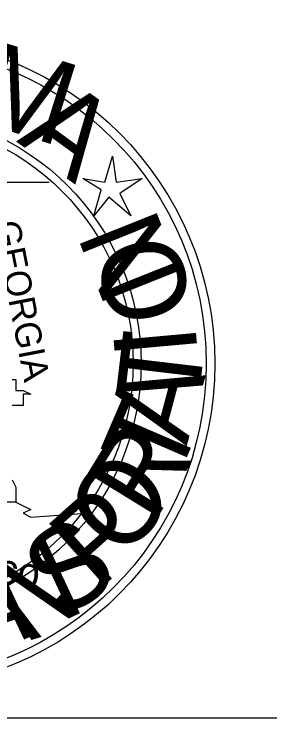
# Model space of a CAD drawing. Extents: x 1797478 to 1804836, y 246529 to 250952.
# Drawn here: x 1802983.3 to 1802986.92, y 250069.42 to 250079.37 of the extents above; entities that cross this region are included whole.
import ezdxf

# ---------------------------------------------------------------- set-up
doc = ezdxf.new("R2010")
doc.units = 0
doc.layers.add('great seal', color=7, linetype='Continuous')
doc.layers.add('SHT-BNDRY', color=7, linetype='Continuous')

msp = doc.modelspace()

# ---------------------------------------------------------------- linework, layer by layer
at = {"layer": 'great seal'}
msp.add_line((1802982.5334, 250076.9902), (1802983.7947, 250076.9902), dxfattribs=at)
msp.add_line((1802982.5334, 250076.9902), (1802983.7947, 250076.9902), dxfattribs=at)
msp.add_line((1802982.5334, 250076.9902), (1802983.7947, 250076.9902), dxfattribs=at)
msp.add_lwpolyline([(1802984.688, 250077.358), (1802984.7406, 250076.9902), (1802985.1085, 250077.0427), (1802984.7932, 250076.8325), (1802984.9508, 250076.5172), (1802984.6355, 250076.78), (1802984.4253, 250076.5172), (1802984.5304, 250076.8851), (1802984.2676, 250077.0427), (1802984.5829, 250076.9902)], close=True, dxfattribs=at)
msp.add_lwpolyline([(1802984.688, 250077.358), (1802984.7406, 250076.9902), (1802985.1085, 250077.0427), (1802984.7932, 250076.8325), (1802984.9508, 250076.5172), (1802984.6355, 250076.78), (1802984.4253, 250076.5172), (1802984.5304, 250076.8851), (1802984.2676, 250077.0427), (1802984.5829, 250076.9902)], close=True, dxfattribs=at)
msp.add_lwpolyline([(1802984.688, 250077.358), (1802984.7406, 250076.9902), (1802985.1085, 250077.0427), (1802984.7932, 250076.8325), (1802984.9508, 250076.5172), (1802984.6355, 250076.78), (1802984.4253, 250076.5172), (1802984.5304, 250076.8851), (1802984.2676, 250077.0427), (1802984.5829, 250076.9902)], close=True, dxfattribs=at)
for points in [[(1802983.2691, 250074.2049), (1802983.3217, 250074.2049), (1802983.3217, 250074.1523), (1802983.3217, 250074.1523), (1802983.3217, 250074.0998), (1802983.3217, 250074.0472), (1802983.4268, 250074.0472), (1802983.5319, 250073.9947), (1802983.4268, 250073.9947), (1802983.4268, 250073.837), (1802983.4268, 250073.837), (1802983.3217, 250073.837), (1802983.3217, 250073.837), (1802983.3217, 250073.837), (1802983.3217, 250073.837), (1802983.2691, 250073.837)], [(1802983.2691, 250074.2049), (1802983.3217, 250074.2049), (1802983.3217, 250074.1523), (1802983.3217, 250074.1523), (1802983.3217, 250074.0998), (1802983.3217, 250074.0472), (1802983.4268, 250074.0472), (1802983.5319, 250073.9947), (1802983.4268, 250073.9947), (1802983.4268, 250073.837), (1802983.4268, 250073.837), (1802983.3217, 250073.837), (1802983.3217, 250073.837), (1802983.3217, 250073.837), (1802983.3217, 250073.837), (1802983.2691, 250073.837)], [(1802983.2691, 250074.2049), (1802983.3217, 250074.2049), (1802983.3217, 250074.1523), (1802983.3217, 250074.1523), (1802983.3217, 250074.0998), (1802983.3217, 250074.0472), (1802983.4268, 250074.0472), (1802983.5319, 250073.9947), (1802983.4268, 250073.9947), (1802983.4268, 250073.837), (1802983.4268, 250073.837), (1802983.3217, 250073.837), (1802983.3217, 250073.837), (1802983.3217, 250073.837), (1802983.3217, 250073.837), (1802983.2691, 250073.837)], [(1802983.2691, 250072.786), (1802983.3217, 250072.6809), (1802983.3217, 250072.6809), (1802983.3217, 250072.6283), (1802983.3217, 250072.6283), (1802983.3217, 250072.4706), (1802980.6415, 250072.4706)], [(1802983.2691, 250072.786), (1802983.3217, 250072.6809), (1802983.3217, 250072.6809), (1802983.3217, 250072.6283), (1802983.3217, 250072.6283), (1802983.3217, 250072.4706), (1802980.6415, 250072.4706)], [(1802983.2691, 250072.786), (1802983.3217, 250072.6809), (1802983.3217, 250072.6809), (1802983.3217, 250072.6283), (1802983.3217, 250072.6283), (1802983.3217, 250072.4706), (1802980.6415, 250072.4706)], [(1802983.3217, 250072.4706), (1802983.4268, 250072.4181), (1802983.4268, 250072.4181), (1802983.5319, 250072.3655), (1802983.4268, 250072.313), (1802983.5319, 250072.2604), (1802984.3202, 250072.313)], [(1802983.3217, 250072.4706), (1802983.4268, 250072.4181), (1802983.4268, 250072.4181), (1802983.5319, 250072.3655), (1802983.4268, 250072.313), (1802983.5319, 250072.2604), (1802984.3202, 250072.313)], [(1802983.3217, 250072.4706), (1802983.4268, 250072.4181), (1802983.4268, 250072.4181), (1802983.5319, 250072.3655), (1802983.4268, 250072.313), (1802983.5319, 250072.2604), (1802984.3202, 250072.313)]]:
    msp.add_lwpolyline(points, dxfattribs=at)
for radius in [4.5988, 4.5988, 4.5988, 4.4778, 4.4778, 4.4778, 3.5557, 3.5557, 3.5557, 3.4444, 3.4444, 3.4444]:
    msp.add_circle((1802981.5384, 250074.4308), radius, dxfattribs=at)
at = {"layer": 'SHT-BNDRY'}
msp.add_lwpolyline([(1802808.5046, 250069.422), (1803131.0046, 250069.422), (1803131.0046, 250279.422), (1802808.5046, 250279.422)], close=True, dxfattribs=at)

# ---------------------------------------------------------------- texts
at = {"layer": 'great seal'}
for s, height, rotation, p in [('M', 1.1701, 342.59208, (1802982.691, 250077.8836)), ('A', 1.1695, 323.98869, (1802983.3217, 250077.5683)), ('A', 1.1695, 323.98869, (1802983.3217, 250077.5683)), ('A', 1.1695, 323.98869, (1802983.3217, 250077.5683)), ('N', 1.1701, 111.72097, (1802985.6866, 250075.6238)), ('N', 1.1701, 111.72097, (1802985.6866, 250075.6238)), ('N', 1.1701, 111.72097, (1802985.6866, 250075.6238)), ('GEORGIA', 0.36892, 280.92962, (1802983.0064, 250076.4121)), ('GEORGIA', 0.36892, 280.92962, (1802983.0064, 250076.4121)), ('GEORGIA', 0.36892, 280.92962, (1802983.0064, 250076.4121)), ('O', 1.1701, 103.43258, (1802985.8442, 250075.1508)), ('O', 1.1701, 103.43258, (1802985.8442, 250075.1508)), ('O', 1.1701, 103.43258, (1802985.8442, 250075.1508)), ('I', 1.1701, 95.14419, (1802985.8968, 250074.5728)), ('I', 1.1701, 95.14419, (1802985.8968, 250074.5728)), ('I', 1.1701, 95.14419, (1802985.8968, 250074.5728)), ('T', 1.1701, 83.25653, (1802985.8968, 250073.837)), ('T', 1.1701, 83.25653, (1802985.8968, 250073.837)), ('T', 1.1701, 83.25653, (1802985.8968, 250073.837)), ('A', 1.1701, 74.96814, (1802985.7391, 250073.2589)), ('A', 1.1701, 74.96814, (1802985.7391, 250073.2589)), ('A', 1.1701, 74.96814, (1802985.7391, 250073.2589)), ('T', 1.1695, 66.67975, (1802985.5814, 250072.7334)), ('R', 1.1701, 58.39136, (1802985.2661, 250072.1553)), ('O', 1.1701, 50.10297, (1802984.8457, 250071.6298)), ('O', 1.1701, 50.10297, (1802984.8457, 250071.6298)), ('O', 1.1701, 50.10297, (1802984.8457, 250071.6298)), ('P', 1.1701, 41.81458, (1802984.4778, 250071.2094)), ('P', 1.1701, 41.81458, (1802984.4778, 250071.2094)), ('P', 1.1701, 41.81458, (1802984.4778, 250071.2094)), ('S', 1.1701, 33.52619, (1802983.9523, 250070.789)), ('S', 1.1701, 33.52619, (1802983.9523, 250070.789)), ('S', 1.1701, 33.52619, (1802983.9523, 250070.789)), ('N', 1.1701, 25.23781, (1802983.3217, 250070.4736)), ('N', 1.1701, 25.23781, (1802983.3217, 250070.4736)), ('N', 1.1701, 25.23781, (1802983.3217, 250070.4736)), ('Mexico', 0.42568, 351.00003, (1802981.8502, 250071.5247)), ('Mexico', 0.42568, 351.00003, (1802981.8502, 250071.5247)), ('Mexico', 0.42568, 351.00003, (1802981.8502, 250071.5247)), ('A', 1.1695, 16.94942, (1802982.691, 250070.2634)), ('A', 1.1695, 16.94942, (1802982.691, 250070.2634)), ('A', 1.1695, 16.94942, (1802982.691, 250070.2634))]:
    msp.add_text(s, height=height, rotation=rotation, dxfattribs=at).set_placement(p)

doc.saveas('drawing.dxf')
